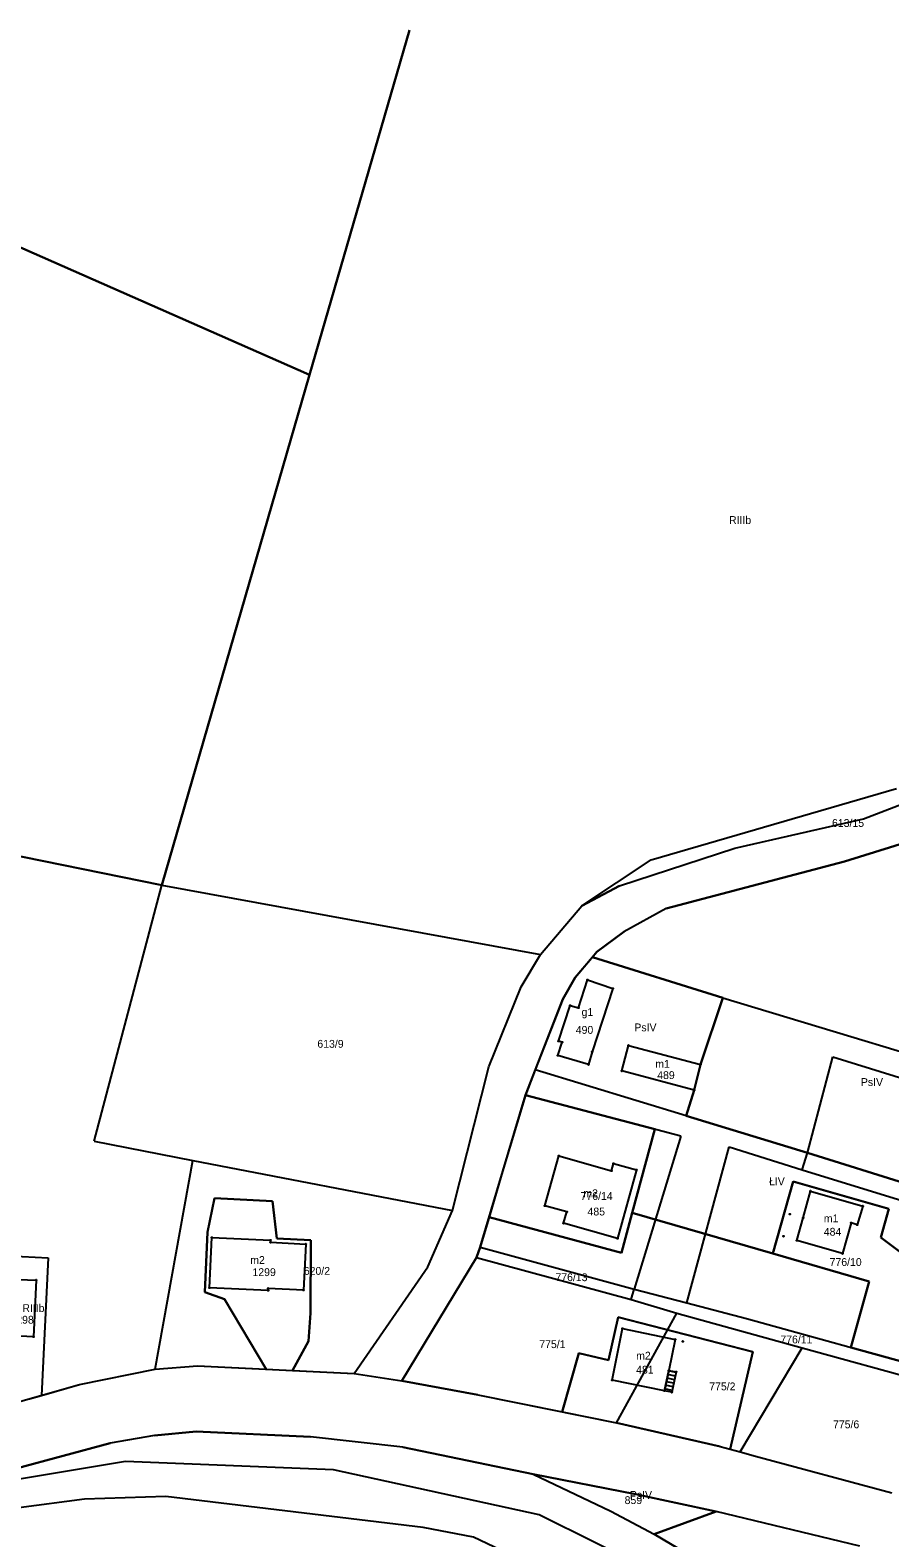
# Model space of a CAD drawing. Extents: x 7498273 to 7499989, y 5499795 to 5500810.
# Drawn here: x 7498893.9 to 7499058.4, y 5500521 to 5500809.6 of the extents above; entities that cross this region are included whole.
import ezdxf

# ---------------------------------------------------------------- set-up
doc = ezdxf.new("R2010")
doc.units = 0
for name, color, linetype in [('209-oznaczenie konturu klasyfikacyjnego', 7, 'Continuous'), ('211-numer działki ewidencyjnej', 7, 'Continuous'), ('217-kontur klasyfikacyjny', 7, 'Continuous'), ('218-kontur użytku gruntowego', 7, 'Continuous'), ('219-działka ewidencyjna', 7, 'Continuous'), ('312-budynek ewidencyjny', 7, 'Continuous'), ('312-oznaczenie budynku ewidencyjnego', 7, 'Continuous'), ('312-oznaczenie budynku ewidencyjnego-Atr117', 7, 'Continuous'), ('352-schody', 7, 'Continuous'), ('Punkt budynku', 7, 'Continuous')]:
    doc.layers.add(name, color=color, linetype=linetype)

# ---------------------------------------------------------------- blocks, each defined once
blk = doc.blocks.new('PUNKTBUD')
blk.add_circle((0, 0), 0.09)

msp = doc.modelspace()

# ---------------------------------------------------------------- linework, layer by layer
at = {"layer": '217-kontur klasyfikacyjny'}
for points in [[(7498966.458, 5500809.555), (7498947.36, 5500743.6)], [(7498947.36, 5500743.6), (7498877.37, 5500774.38)], [(7498919.07, 5500645.93), (7498947.36, 5500743.6)], [(7499053.34, 5500658.62), (7499068.25, 5500664.35)], [(7498843.43, 5500661.3), (7498919.07, 5500645.93)], [(7499028.75, 5500653.01), (7499053.34, 5500658.62)], [(7499062.21, 5500654.31), (7499049.68, 5500650.43)], [(7499006.66, 5500645.8), (7499028.75, 5500653.01)], [(7499049.68, 5500650.43), (7499015.61, 5500641.43)], [(7498999.43, 5500641.92), (7499006.66, 5500645.8)], [(7498991.57, 5500632.66), (7498999.43, 5500641.92)], [(7499015.61, 5500641.43), (7499007.48, 5500636.96)], [(7499007.48, 5500636.96), (7499002.3, 5500633.12)], [(7498987.85, 5500626.41), (7498991.57, 5500632.66)], [(7499001.47, 5500632.14), (7498998.19, 5500628.24)], [(7499002.3, 5500633.12), (7499001.47, 5500632.14)], [(7499026.45, 5500624.36), (7499001.47, 5500632.14)], [(7498998.19, 5500628.24), (7498995.84, 5500624.07)], [(7498981.63, 5500611.13), (7498987.85, 5500626.41)], [(7498995.84, 5500624.07), (7498990.55, 5500610.54)], [(7499022.13, 5500611.55), (7499026.45, 5500624.36)], [(7499026.45, 5500624.36), (7499084.28, 5500606.88)], [(7498974.69, 5500583.63), (7498981.63, 5500611.13)], [(7498990.55, 5500610.54), (7498988.67, 5500605.72)], [(7499019.41, 5500601.72), (7498990.55, 5500610.54)], [(7499020.93, 5500606.65), (7499022.13, 5500611.55)], [(7498988.67, 5500605.72), (7499013.39, 5500599.18)], [(7499019.41, 5500601.72), (7499020.93, 5500606.65)], [(7499042.6, 5500594.64), (7499019.41, 5500601.72)], [(7499013.39, 5500599.18), (7499009.1, 5500583.19)], [(7499062.19, 5500588.57), (7499042.6, 5500594.64)], [(7499036.02, 5500575.39), (7499039.9, 5500589.15)], [(7499039.9, 5500589.15), (7499058.18, 5500583.93)], [(7498927.81, 5500579.51), (7498929.14, 5500585.98)], [(7498929.14, 5500585.98), (7498940.25, 5500585.41)], [(7498940.25, 5500585.41), (7498941.08, 5500578.28)], [(7498970.01, 5500572.84), (7498974.69, 5500583.63)], [(7498981.69, 5500582.34), (7498979.99, 5500576.63)], [(7499007.04, 5500575.5), (7498981.69, 5500582.34)], [(7499009.1, 5500583.19), (7499007.04, 5500575.5)], [(7499036.02, 5500575.39), (7499009.1, 5500583.19)], [(7499058.18, 5500583.93), (7499056.67, 5500578.45)], [(7498927.33, 5500568.02), (7498927.81, 5500579.51)], [(7499056.67, 5500578.45), (7499064.09, 5500572.94)], [(7498941.08, 5500578.28), (7498947.57, 5500577.97)], [(7498947.57, 5500577.97), (7498947.51, 5500563.99)], [(7498979.99, 5500576.63), (7498979.32, 5500574.62)], [(7498884.84, 5500575.23), (7498897.31, 5500574.57)], [(7498897.31, 5500574.57), (7498896.05, 5500548.23)], [(7498955.89, 5500552.4), (7498970.01, 5500572.84)], [(7498979.32, 5500574.62), (7498964.99, 5500551.01)], [(7499054.43, 5500570.06), (7499036.02, 5500575.39)], [(7499050.92, 5500557.41), (7499054.43, 5500570.06)], [(7498931.05, 5500566.63), (7498927.33, 5500568.02)], [(7498939.03, 5500553.25), (7498931.05, 5500566.63)], [(7498947.51, 5500563.99), (7498947.17, 5500558.64)], [(7499004.56, 5500554.98), (7499006.43, 5500563.23)], [(7499006.43, 5500563.23), (7499032.16, 5500556.55)], [(7498947.17, 5500558.64), (7498944.11, 5500552.99)], [(7498995.68, 5500545.09), (7498998.85, 5500556.34)], [(7498998.85, 5500556.34), (7499004.56, 5500554.98)], [(7499032.16, 5500556.55), (7499027.81, 5500537.95)], [(7499065.99, 5500553.24), (7499050.92, 5500557.41)], [(7498903.35, 5500550.3), (7498917.81, 5500553.25)], [(7498917.81, 5500553.25), (7498925.88, 5500553.91)], [(7498925.88, 5500553.91), (7498939.03, 5500553.25)], [(7498944.11, 5500552.99), (7498955.89, 5500552.4)], [(7498896.05, 5500548.23), (7498903.35, 5500550.3)], [(7498964.99, 5500551.01), (7498979.53, 5500548.38)], [(7498893.74, 5500547.57), (7498896.05, 5500548.23)], [(7498979.53, 5500548.38), (7498995.68, 5500545.09)], [(7499027.81, 5500537.95), (7499029.76, 5500537.43)], [(7499029.76, 5500537.43), (7499032.7, 5500536.58)], [(7499032.7, 5500536.58), (7499058.78, 5500529.56)], [(7498990.12, 5500533.17), (7499005.03, 5500526.11)], [(7499009.75, 5500529.33), (7498990.12, 5500533.17)], [(7499025.15, 5500526.01), (7499009.75, 5500529.33)], [(7499005.03, 5500526.11), (7499013.3, 5500521.7)], [(7499013.3, 5500521.7), (7499025.15, 5500526.01)], [(7499052.63, 5500519.38), (7499025.15, 5500526.01)], [(7499013.3, 5500521.7), (7499024.04, 5500515.33)]]:
    msp.add_lwpolyline(points, dxfattribs=at)
at = {"layer": '218-kontur użytku gruntowego'}
for points in [[(7498947.36, 5500743.6), (7498966.458, 5500809.555)], [(7498877.37, 5500774.38), (7498947.36, 5500743.6)], [(7498947.36, 5500743.6), (7498919.07, 5500645.93)], [(7499053.34, 5500658.62), (7499068.25, 5500664.35)], [(7498919.07, 5500645.93), (7498843.43, 5500661.3)], [(7499028.75, 5500653.01), (7499053.34, 5500658.62)], [(7499062.21, 5500654.31), (7499049.68, 5500650.43)], [(7499006.66, 5500645.8), (7499028.75, 5500653.01)], [(7499049.68, 5500650.43), (7499015.61, 5500641.43)], [(7498999.43, 5500641.92), (7499006.66, 5500645.8)], [(7498991.57, 5500632.66), (7498999.43, 5500641.92)], [(7499015.61, 5500641.43), (7499007.48, 5500636.96)], [(7499007.48, 5500636.96), (7499002.3, 5500633.12)], [(7498987.85, 5500626.41), (7498991.57, 5500632.66)], [(7499001.47, 5500632.14), (7498998.19, 5500628.24)], [(7499002.3, 5500633.12), (7499001.47, 5500632.14)], [(7499001.47, 5500632.14), (7499026.45, 5500624.36)], [(7498998.19, 5500628.24), (7498995.84, 5500624.07)], [(7498981.63, 5500611.13), (7498987.85, 5500626.41)], [(7498995.84, 5500624.07), (7498990.55, 5500610.54)], [(7499026.45, 5500624.36), (7499022.13, 5500611.55)], [(7499026.45, 5500624.36), (7499084.28, 5500606.88)], [(7498974.69, 5500583.63), (7498981.63, 5500611.13)], [(7498990.55, 5500610.54), (7498988.67, 5500605.72)], [(7499019.41, 5500601.72), (7498990.55, 5500610.54)], [(7499022.13, 5500611.55), (7499020.93, 5500606.65)], [(7498988.67, 5500605.72), (7498984.11, 5500590.44)], [(7499013.39, 5500599.18), (7498988.67, 5500605.72)], [(7499020.93, 5500606.65), (7499019.41, 5500601.72)], [(7499019.41, 5500601.72), (7499042.6, 5500594.64)], [(7499009.1, 5500583.19), (7499013.39, 5500599.18)], [(7499042.6, 5500594.64), (7499062.19, 5500588.57)], [(7498984.11, 5500590.44), (7498981.69, 5500582.34)], [(7499039.9, 5500589.15), (7499036.02, 5500575.39)], [(7499058.18, 5500583.93), (7499039.9, 5500589.15)], [(7498929.14, 5500585.98), (7498927.81, 5500579.51)], [(7498940.25, 5500585.41), (7498929.14, 5500585.98)], [(7498941.08, 5500578.28), (7498940.25, 5500585.41)], [(7498970.01, 5500572.84), (7498974.69, 5500583.63)], [(7498981.69, 5500582.34), (7498979.99, 5500576.63)], [(7498981.69, 5500582.34), (7499007.04, 5500575.5)], [(7499007.04, 5500575.5), (7499009.1, 5500583.19)], [(7499009.1, 5500583.19), (7499036.02, 5500575.39)], [(7499056.67, 5500578.45), (7499058.18, 5500583.93)], [(7498927.81, 5500579.51), (7498927.33, 5500568.02)], [(7499064.09, 5500572.94), (7499056.67, 5500578.45)], [(7498947.57, 5500577.97), (7498941.08, 5500578.28)], [(7498947.51, 5500563.99), (7498947.57, 5500577.97)], [(7498979.99, 5500576.63), (7498979.32, 5500574.62)], [(7498884.84, 5500575.23), (7498897.31, 5500574.57)], [(7498897.31, 5500574.57), (7498896.05, 5500548.23)], [(7498955.89, 5500552.4), (7498970.01, 5500572.84)], [(7498979.32, 5500574.62), (7498964.99, 5500551.01)], [(7499036.02, 5500575.39), (7499054.43, 5500570.06)], [(7499054.43, 5500570.06), (7499050.92, 5500557.41)], [(7498927.33, 5500568.02), (7498931.05, 5500566.63)], [(7498931.05, 5500566.63), (7498939.03, 5500553.25)], [(7498947.17, 5500558.64), (7498947.51, 5500563.99)], [(7499006.43, 5500563.23), (7499004.56, 5500554.98)], [(7499032.16, 5500556.55), (7499006.43, 5500563.23)], [(7498944.11, 5500552.99), (7498947.17, 5500558.64)], [(7498998.85, 5500556.34), (7498995.68, 5500545.09)], [(7499004.56, 5500554.98), (7498998.85, 5500556.34)], [(7499027.81, 5500537.95), (7499032.16, 5500556.55)], [(7499050.92, 5500557.41), (7499065.99, 5500553.24)], [(7498903.35, 5500550.3), (7498917.81, 5500553.25)], [(7498917.81, 5500553.25), (7498925.88, 5500553.91)], [(7498925.88, 5500553.91), (7498939.03, 5500553.25)], [(7498939.03, 5500553.25), (7498944.11, 5500552.99)], [(7498944.11, 5500552.99), (7498955.89, 5500552.4)], [(7498896.05, 5500548.23), (7498903.35, 5500550.3)], [(7498964.99, 5500551.01), (7498979.53, 5500548.38)], [(7498893.74, 5500547.57), (7498896.05, 5500548.23)], [(7498979.53, 5500548.38), (7498995.68, 5500545.09)], [(7498995.68, 5500545.09), (7499006.07, 5500542.98)], [(7498925.65, 5500541.3), (7498917.67, 5500540.59)], [(7498947.52, 5500540.34), (7498925.65, 5500541.3)], [(7499006.07, 5500542.98), (7499025.94, 5500538.44)], [(7498909.17, 5500539.12), (7498891.23, 5500534.26)], [(7498917.67, 5500540.59), (7498909.17, 5500539.12)], [(7498965.22, 5500538.3), (7498947.52, 5500540.34)], [(7498990.12, 5500533.17), (7498965.22, 5500538.3)], [(7499025.94, 5500538.44), (7499027.81, 5500537.95)], [(7498912.14, 5500535.6), (7498883.39, 5500530.82)], [(7498951.94, 5500534.02), (7498912.14, 5500535.6)], [(7499027.81, 5500537.95), (7499029.76, 5500537.43)], [(7499029.76, 5500537.43), (7499032.7, 5500536.58)], [(7499032.7, 5500536.58), (7499058.78, 5500529.56)], [(7498991.26, 5500525.39), (7498951.94, 5500534.02)], [(7498990.12, 5500533.17), (7499005.03, 5500526.11)], [(7499009.75, 5500529.33), (7498990.12, 5500533.17)], [(7499025.15, 5500526.01), (7499009.75, 5500529.33)], [(7498904.28, 5500528.36), (7498891.73, 5500526.7)], [(7498919.82, 5500528.92), (7498904.28, 5500528.36)], [(7498969.1, 5500522.98), (7498919.82, 5500528.92)], [(7499012.84, 5500514.68), (7498991.26, 5500525.39)], [(7499005.03, 5500526.11), (7499013.3, 5500521.7)], [(7499025.15, 5500526.01), (7499013.3, 5500521.7)], [(7499052.63, 5500519.38), (7499025.15, 5500526.01)], [(7498978.75, 5500521.1), (7498969.1, 5500522.98)], [(7499007.17, 5500507.58), (7498978.75, 5500521.1)], [(7499013.3, 5500521.7), (7499024.04, 5500515.33)]]:
    msp.add_lwpolyline(points, dxfattribs=at)
at = {"layer": '219-działka ewidencyjna'}
for points in [[(7498919.07, 5500645.93), (7498966.456, 5500809.555)], [(7498820.57, 5500665.94), (7498919.07, 5500645.93)], [(7499012.72, 5500650.77), (7499059.63, 5500664.38)], [(7499053.34, 5500658.62), (7499068.25, 5500664.35)], [(7499028.75, 5500653.01), (7499053.34, 5500658.62)], [(7499049.68, 5500650.43), (7499062.21, 5500654.31)], [(7498999.43, 5500641.92), (7499012.72, 5500650.77)], [(7499006.66, 5500645.8), (7499028.75, 5500653.01)], [(7499015.61, 5500641.43), (7499049.68, 5500650.43)], [(7498906.13, 5500596.93), (7498919.07, 5500645.93)], [(7498919.07, 5500645.93), (7498991.57, 5500632.66)], [(7499006.66, 5500645.8), (7498999.43, 5500641.92)], [(7498991.57, 5500632.66), (7498999.43, 5500641.92)], [(7499015.61, 5500641.43), (7499007.48, 5500636.96)], [(7499002.3, 5500633.12), (7499007.48, 5500636.96)], [(7498987.85, 5500626.41), (7498991.57, 5500632.66)], [(7498998.19, 5500628.24), (7499002.3, 5500633.12)], [(7498995.84, 5500624.07), (7498998.19, 5500628.24)], [(7498981.63, 5500611.13), (7498987.85, 5500626.41)], [(7498988.67, 5500605.72), (7498995.84, 5500624.07)], [(7499042.6, 5500594.64), (7499047.5, 5500613.05)], [(7499047.5, 5500613.05), (7499100.8, 5500596.5)], [(7498974.69, 5500583.63), (7498981.63, 5500611.13)], [(7498979.99, 5500576.63), (7498988.67, 5500605.72)], [(7499018.42, 5500597.85), (7498988.67, 5500605.72)], [(7498906.13, 5500596.93), (7498925.01, 5500593.23)], [(7499018.42, 5500597.85), (7499009.47, 5500568.58)], [(7499019.57, 5500565.97), (7499027.66, 5500595.8)], [(7499027.66, 5500595.8), (7499041.62, 5500591.43)], [(7498917.81, 5500553.25), (7498925.01, 5500593.23)], [(7498925.01, 5500593.23), (7498974.69, 5500583.63)], [(7499041.62, 5500591.43), (7499042.6, 5500594.64)], [(7499042.6, 5500594.64), (7499075.36, 5500584.48)], [(7499041.62, 5500591.43), (7499074.15, 5500581.4)], [(7498970.01, 5500572.84), (7498974.69, 5500583.63)], [(7498979.32, 5500574.62), (7498979.99, 5500576.63)], [(7498979.99, 5500576.63), (7499009.47, 5500568.58)], [(7498955.89, 5500552.4), (7498970.01, 5500572.84)], [(7498964.99, 5500551.01), (7498979.32, 5500574.62)], [(7498979.32, 5500574.62), (7499008.88, 5500566.58)], [(7499008.88, 5500566.58), (7499009.47, 5500568.58)], [(7499009.47, 5500568.58), (7499019.57, 5500565.97)], [(7499006.07, 5500542.98), (7499017.63, 5500563.99)], [(7499008.88, 5500566.58), (7499017.63, 5500563.99)], [(7499017.63, 5500563.99), (7499041.59, 5500557.33)], [(7499019.57, 5500565.97), (7499030.97, 5500562.93)], [(7499030.97, 5500562.93), (7499065.99, 5500553.24)], [(7499029.76, 5500537.43), (7499041.59, 5500557.33)], [(7499041.59, 5500557.33), (7499065.28, 5500550.81)], [(7498903.35, 5500550.3), (7498917.81, 5500553.25)], [(7498917.81, 5500553.25), (7498925.88, 5500553.91)], [(7498925.88, 5500553.91), (7498955.89, 5500552.4)], [(7498955.89, 5500552.4), (7498964.99, 5500551.01)], [(7498880.64, 5500543.86), (7498903.35, 5500550.3)], [(7498979.53, 5500548.38), (7498964.99, 5500551.01)], [(7498979.53, 5500548.38), (7499006.07, 5500542.98)], [(7498917.67, 5500540.59), (7498925.65, 5500541.3)], [(7498925.65, 5500541.3), (7498947.52, 5500540.34)], [(7499025.94, 5500538.44), (7499006.07, 5500542.98)], [(7498891.23, 5500534.26), (7498909.17, 5500539.12)], [(7498917.67, 5500540.59), (7498909.17, 5500539.12)], [(7498965.22, 5500538.3), (7498947.52, 5500540.34)], [(7498965.22, 5500538.3), (7498990.12, 5500533.17)], [(7499025.94, 5500538.44), (7499029.76, 5500537.43)], [(7499029.76, 5500537.43), (7499032.7, 5500536.58)], [(7499032.7, 5500536.58), (7499058.78, 5500529.56)], [(7498990.12, 5500533.17), (7499009.75, 5500529.33)], [(7498990.12, 5500533.17), (7499005.03, 5500526.11)], [(7499009.75, 5500529.33), (7499025.15, 5500526.01)], [(7499005.03, 5500526.11), (7499013.3, 5500521.7)], [(7499013.3, 5500521.7), (7499025.15, 5500526.01)], [(7499052.63, 5500519.38), (7499025.15, 5500526.01)], [(7499024.04, 5500515.33), (7499013.3, 5500521.7)]]:
    msp.add_lwpolyline(points, dxfattribs=at)
at = {"layer": '312-budynek ewidencyjny'}
for points in [[(7498998.79, 5500622.43), (7499000.53, 5500627.75)], [(7499000.53, 5500627.75), (7499005.37, 5500626.12)], [(7499005.37, 5500626.12), (7499001.43, 5500613.99)], [(7498994.97, 5500616.07), (7498997.23, 5500622.87)], [(7498997.23, 5500622.87), (7498998.79, 5500622.43)], [(7498995.66, 5500615.85), (7498994.97, 5500616.07)], [(7498994.84, 5500613.33), (7498995.66, 5500615.85)], [(7499000.74, 5500611.55), (7498994.84, 5500613.33)], [(7499001.43, 5500613.99), (7499000.74, 5500611.55)], [(7499007.13, 5500610.34), (7499008.41, 5500615.23)], [(7499008.41, 5500615.23), (7499022.13, 5500611.55)], [(7499020.93, 5500606.65), (7499007.13, 5500610.34)], [(7499022.13, 5500611.55), (7499020.93, 5500606.65)], [(7498992.38, 5500584.55), (7498995.06, 5500594.08)], [(7498995.06, 5500594.08), (7499005.12, 5500591.25)], [(7499005.12, 5500591.25), (7499005.51, 5500592.63)], [(7499005.51, 5500592.63), (7499009.94, 5500591.4)], [(7499009.94, 5500591.4), (7499006.25, 5500578.27)], [(7499041.78, 5500582.24), (7499043.22, 5500587.35)], [(7499043.22, 5500587.35), (7499053.19, 5500584.47)], [(7498996.57, 5500583.37), (7498992.38, 5500584.55)], [(7499053.19, 5500584.47), (7499052.16, 5500580.91)], [(7498995.96, 5500581.2), (7498996.57, 5500583.37)], [(7499040.56, 5500577.91), (7499041.78, 5500582.24)], [(7499051, 5500581.25), (7499049.31, 5500575.39)], [(7499052.16, 5500580.91), (7499051, 5500581.25)], [(7498928.18, 5500568.85), (7498928.66, 5500578.46)], [(7498928.66, 5500578.46), (7498939.9, 5500577.95)], [(7499006.25, 5500578.27), (7498995.96, 5500581.2)], [(7498939.9, 5500577.95), (7498939.88, 5500577.55)], [(7498939.88, 5500577.55), (7498946.66, 5500577.2)], [(7498946.66, 5500577.2), (7498946.21, 5500568.41)], [(7499049.31, 5500575.39), (7499040.56, 5500577.91)], [(7498888.46, 5500570.56), (7498895.01, 5500570.31)], [(7498895.01, 5500570.31), (7498894.52, 5500559.48)], [(7498939.4, 5500568.34), (7498928.18, 5500568.85)], [(7498939.42, 5500568.73), (7498939.4, 5500568.34)], [(7498946.21, 5500568.41), (7498939.42, 5500568.73)], [(7498894.52, 5500559.48), (7498887.95, 5500559.77)], [(7499005.23, 5500551.16), (7499007.25, 5500561.03)], [(7499007.25, 5500561.03), (7499017.28, 5500558.95)], [(7499017.28, 5500558.95), (7499016.07, 5500553.03)], [(7499016.07, 5500553.03), (7499015.27, 5500549.14)], [(7499015.27, 5500549.14), (7499005.23, 5500551.16)]]:
    msp.add_lwpolyline(points, dxfattribs=at)
at = {"layer": '352-schody'}
msp.add_lwpolyline([(7499015.27, 5500549.14), (7499016.07, 5500553.03), (7499017.48, 5500552.74), (7499016.68, 5500548.85)], close=True, dxfattribs=at)
msp.add_lwpolyline([(7499015.27, 5500549.14), (7499016.07, 5500553.03), (7499017.48, 5500552.74), (7499016.68, 5500548.85)], close=True, dxfattribs=at)
for points in [[(7499017.456, 5500552.621), (7499016.046, 5500552.911)], [(7499016.892, 5500549.879), (7499015.482, 5500550.168)], [(7499017.033, 5500550.564), (7499015.623, 5500550.854)], [(7499017.174, 5500551.25), (7499015.764, 5500551.54)], [(7499017.315, 5500551.935), (7499015.905, 5500552.225)], [(7499016.751, 5500549.193), (7499015.341, 5500549.483)]]:
    msp.add_lwpolyline(points, dxfattribs=at)

# ---------------------------------------------------------------- block references
at = {"layer": 'Punkt budynku'}
for p in [(7499000.53, 5500627.75), (7499005.37, 5500626.12), (7498997.23, 5500622.87), (7498998.79, 5500622.43), (7498994.97, 5500616.07), (7498995.66, 5500615.85), (7498994.84, 5500613.33), (7499001.43, 5500613.99), (7499008.41, 5500615.23), (7499000.74, 5500611.55), (7499007.13, 5500610.34), (7499022.13, 5500611.55), (7499020.93, 5500606.65), (7498995.06, 5500594.08), (7499005.12, 5500591.25), (7499005.51, 5500592.63), (7499009.94, 5500591.4), (7499043.22, 5500587.35), (7498992.38, 5500584.55), (7499053.19, 5500584.47), (7498995.96, 5500581.2), (7498996.57, 5500583.37), (7499039.24, 5500582.93), (7499041.78, 5500582.24), (7499051, 5500581.25), (7498928.66, 5500578.46), (7499006.25, 5500578.27), (7499038.04, 5500578.71), (7499052.16, 5500580.91), (7498939.88, 5500577.55), (7498939.9, 5500577.95), (7498946.66, 5500577.2), (7499040.56, 5500577.91), (7499049.31, 5500575.39), (7498895.01, 5500570.31), (7498928.18, 5500568.85), (7498939.4, 5500568.34), (7498939.42, 5500568.73), (7498946.21, 5500568.41), (7499007.25, 5500561.03), (7498894.52, 5500559.48), (7499017.28, 5500558.95), (7499018.76, 5500558.58), (7499016.07, 5500553.03), (7499017.48, 5500552.74), (7499005.23, 5500551.16), (7499015.27, 5500549.14), (7499016.68, 5500548.85)]:
    msp.add_blockref('PUNKTBUD', p, dxfattribs=at)

# ---------------------------------------------------------------- texts
at = {"layer": '209-oznaczenie konturu klasyfikacyjnego'}
for s, p in [('RIIIb', (7499027.62, 5500715.04)), ('PsIV', (7499009.5, 5500617.93)), ('PsIV', (7499052.85, 5500607.47)), ('ŁIV', (7499035.27, 5500588.47)), ('RIIIb', (7498892.4, 5500564.2)), ('PsIV', (7499008.64, 5500528.44))]:
    msp.add_text(s, height=1.5, dxfattribs=at).set_placement(p)
at = {"layer": '211-numer działki ewidencyjnej'}
for s, p in [('613/15', (7499047.32, 5500657.05)), ('613/9', (7498948.85, 5500614.78)), ('776/14', (7498999.21, 5500585.65)), ('620/2', (7498946.25, 5500571.32)), ('776/10', (7499046.86, 5500573.02)), ('776/13', (7498994.4, 5500570.11)), ('775/1', (7498991.31, 5500557.3)), ('776/11', (7499037.44, 5500558.2)), ('775/2', (7499023.83, 5500549.21)), ('775/6', (7499047.52, 5500541.95)), ('859', (7499007.64, 5500527.44))]:
    msp.add_text(s, height=1.5, dxfattribs=at).set_placement(p)
at = {"layer": '312-oznaczenie budynku ewidencyjnego'}
for s, p in [('490', (7498998.29, 5500617.45)), ('489', (7499013.88, 5500608.79)), ('485', (7499000.54, 5500582.68)), ('484', (7499045.75, 5500578.81)), ('1299', (7498936.43, 5500571.08)), ('1298', (7498890.12, 5500561.97)), ('481', (7499009.84, 5500552.4))]:
    msp.add_text(s, height=1.5, dxfattribs=at).set_placement(p)
at = {"layer": '312-oznaczenie budynku ewidencyjnego-Atr117'}
for s, p in [('g1', (7498999.399, 5500620.87)), ('m1', (7499013.505, 5500610.94)), ('m2', (7498999.746, 5500586.18)), ('m1', (7499045.755, 5500581.37)), ('m2', (7498936.006, 5500573.4)), ('m2', (7499009.846, 5500555.09))]:
    msp.add_text(s, height=1.5, dxfattribs=at).set_placement(p)

doc.saveas('drawing.dxf')
